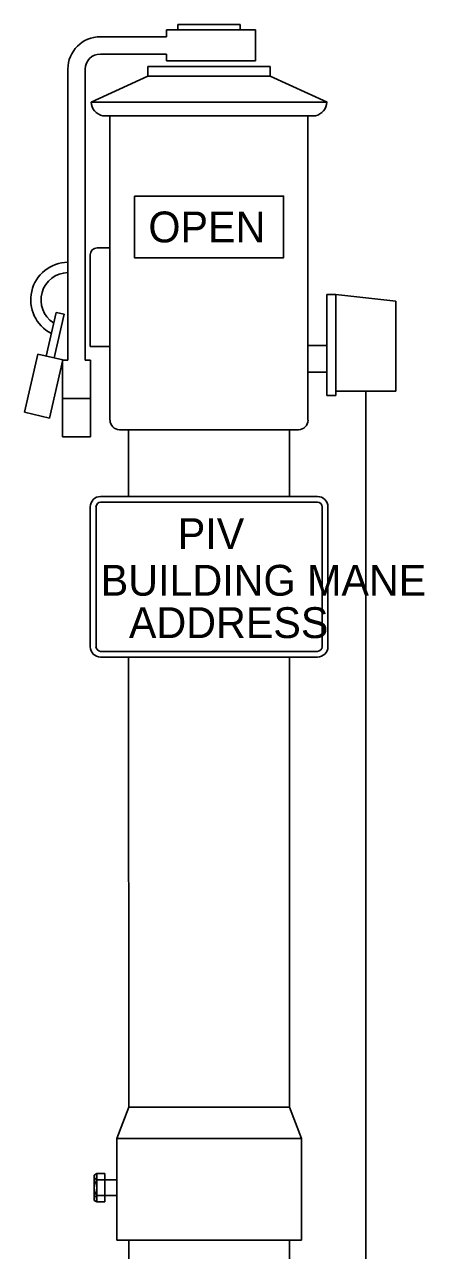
# Model space of a CAD drawing. Extents: x -121875 to -117742, y -103854 to -101122.
# Drawn here: x -119279.8 to -119234.4, y -101508.7 to -101369.5 of the extents above; entities that cross this region are included whole.
import ezdxf

# ---------------------------------------------------------------- set-up
doc = ezdxf.new("R2010")
doc.units = 0
doc.layers.add('Misc CnstDet(22)', color=7, linetype='Continuous')

msp = doc.modelspace()

# ---------------------------------------------------------------- linework, layer by layer
at = {"layer": 'Misc CnstDet(22)'}
for p, q in [((-119262.42, -101370.14), (-119262.42, -101369.52)), ((-119262.42, -101369.52), (-119255.34, -101369.52)), ((-119255.34, -101370.14), (-119255.34, -101369.52)), ((-119263.7, -101370.9), (-119271.19, -101370.9)), ((-119253.62, -101370.14), (-119263.7, -101370.14)), ((-119263.7, -101370.14), (-119263.7, -101370.9)), ((-119262.42, -101369.84), (-119262.42, -101369.84)), ((-119253.62, -101373.63), (-119253.62, -101370.14)), ((-119263.7, -101372.87), (-119271.19, -101372.87)), ((-119263.7, -101372.87), (-119263.7, -101373.63)), ((-119253.62, -101373.63), (-119263.7, -101373.63)), ((-119274.89, -101374.59), (-119274.89, -101407.64)), ((-119272.91, -101374.59), (-119272.91, -101407.64)), ((-119265.82, -101375.38), (-119265.82, -101374.3)), ((-119265.82, -101374.3), (-119251.92, -101374.3)), ((-119251.92, -101375.38), (-119251.92, -101374.3)), ((-119272.25, -101378.34), (-119265.82, -101375.38)), ((-119265.82, -101375.38), (-119251.92, -101375.38)), ((-119245.49, -101378.34), (-119251.92, -101375.38)), ((-119272.25, -101378.34), (-119245.49, -101378.34)), ((-119270.94, -101379.88), (-119246.8, -101379.88)), ((-119270.11, -101414.44), (-119270.11, -101379.88)), ((-119247.65, -101414.44), (-119247.65, -101379.88)), ((-119272.34, -101406.06), (-119272.34, -101395.65)), ((-119271.58, -101394.87), (-119270.11, -101394.87)), ((-119245.51, -101411.64), (-119245.51, -101400.16)), ((-119245.51, -101400.16), (-119244.48, -101400.16)), ((-119244.48, -101411.64), (-119244.48, -101400.16)), ((-119244.48, -101400.16), (-119237.68, -101400.91)), ((-119237.68, -101411.13), (-119237.68, -101400.91)), ((-119276.22, -101402.2), (-119277.34, -101407.16)), ((-119275.32, -101402.41), (-119276.43, -101407.34)), ((-119275.32, -101402.41), (-119276.22, -101402.2)), ((-119278.31, -101406.93), (-119279.8, -101413.54)), ((-119278.31, -101406.93), (-119275.46, -101407.57)), ((-119272.34, -101406.06), (-119270.11, -101406.06)), ((-119245.51, -101405.94), (-119247.65, -101405.94)), ((-119275.46, -101407.57), (-119276.98, -101414.19)), ((-119274.89, -101407.64), (-119275.48, -101407.64)), ((-119275.48, -101407.64), (-119275.48, -101416.32)), ((-119272.91, -101407.64), (-119272.31, -101407.64)), ((-119272.31, -101407.64), (-119272.31, -101416.32)), ((-119245.51, -101409), (-119247.65, -101409)), ((-119244.48, -101411.13), (-119237.68, -101411.13)), ((-119241.08, -101411.13), (-119241.08, -101546.29)), ((-119272.31, -101411.98), (-119275.48, -101411.98)), ((-119245.51, -101411.64), (-119244.48, -101411.64)), ((-119279.8, -101413.54), (-119276.98, -101414.19)), ((-119269.01, -101415.52), (-119248.73, -101415.52)), ((-119268, -101415.52), (-119268, -101423.1)), ((-119249.76, -101415.52), (-119249.76, -101423.1)), ((-119275.48, -101416.32), (-119272.31, -101416.32)), ((-119268, -101441.33), (-119267.97, -101492.41)), ((-119249.76, -101441.33), (-119249.76, -101492.41)), ((-119269.35, -101495.97), (-119267.97, -101492.41)), ((-119267.97, -101492.41), (-119249.76, -101492.41)), ((-119248.38, -101495.97), (-119249.76, -101492.41)), ((-119269.35, -101507.54), (-119269.35, -101495.97)), ((-119269.35, -101495.97), (-119248.38, -101495.97)), ((-119248.38, -101507.54), (-119248.38, -101495.97)), ((-119271.6, -101499.97), (-119271.9, -101500.13)), ((-119271.9, -101503), (-119271.9, -101500.13)), ((-119271.6, -101503.18), (-119271.6, -101499.97)), ((-119271.6, -101499.97), (-119270.68, -101499.97)), ((-119270.68, -101499.97), (-119270.68, -101503.18)), ((-119271.6, -101500.68), (-119269.35, -101500.68)), ((-119271.6, -101503.18), (-119271.9, -101503)), ((-119271.6, -101502.45), (-119269.35, -101502.45)), ((-119270.68, -101503.18), (-119271.6, -101503.18)), ((-119269.35, -101507.54), (-119248.38, -101507.54)), ((-119267.97, -101507.54), (-119268, -101572.63)), ((-119249.76, -101507.54), (-119249.76, -101572.63))]:
    msp.add_line(p, q, dxfattribs=at)
msp.add_lwpolyline([(-119267.33, -101388.99), (-119250.41, -101388.99), (-119250.41, -101396), (-119267.33, -101396)], close=True, dxfattribs=at)
for points in [[(-119271.17, -101423.1), (-119246.57, -101423.1)], [(-119271.17, -101423.74), (-119246.57, -101423.74)], [(-119272.36, -101440.16), (-119272.36, -101424.27)], [(-119271.69, -101440.16), (-119271.69, -101424.27)], [(-119246.04, -101424.27), (-119246.04, -101440.16)], [(-119245.4, -101424.27), (-119245.4, -101440.16)], [(-119246.57, -101440.69), (-119271.17, -101440.69)], [(-119246.57, -101441.33), (-119271.17, -101441.33)]]:
    msp.add_lwpolyline(points, dxfattribs=at)
for centre, radius, start, end in [((-119271.2, -101374.59), 3.69, 90, 180), ((-119271.2, -101374.59), 1.72, 90, 180), ((-119270.62, -101378.28), 1.62, 181.9679, 258.7714), ((-119247.12, -101378.28), 1.62, 281.2286, 358.0321), ((-119271.58, -101395.66), 0.771, 90, 180), ((-119274.83, -101400.78), 4.27, 90.8104, 243.1387), ((-119274.83, -101400.78), 3.1, 91.1158, 237.0081), ((-119269.02, -101414.44), 1.08, 180, 270), ((-119248.72, -101414.44), 1.08, 270, 0), ((-119271.17, -101424.28), 1.18, 90, 180), ((-119271.17, -101424.28), 0.527, 90, 180), ((-119246.57, -101424.28), 1.18, 0, 90), ((-119246.57, -101424.28), 0.527, 0, 90), ((-119271.17, -101440.15), 1.18, 180, 270), ((-119271.17, -101440.15), 0.527, 180, 270), ((-119246.57, -101440.15), 0.527, 270, 0), ((-119246.57, -101440.15), 1.18, 270, 0), ((-119271.47, -101500.29), 0.416, 153.8372, 252.5864), ((-119270.45, -101501.57), 1.44, 142.2115, 217.7885), ((-119271.47, -101502.85), 0.416, 107.4136, 206.1628)]:
    msp.add_arc(centre, radius, start, end, dxfattribs=at)

# ---------------------------------------------------------------- texts
for s, p in [('OPEN', (-119265.75, -101394.25)), ('PIV', (-119262.42, -101429.07)), ('BUILDING MANE', (-119271.16, -101434.36)), ('ADDRESS', (-119267.96, -101439.17))]:
    msp.add_text(s, height=3.5, dxfattribs=at).set_placement(p)

doc.saveas('drawing.dxf')
